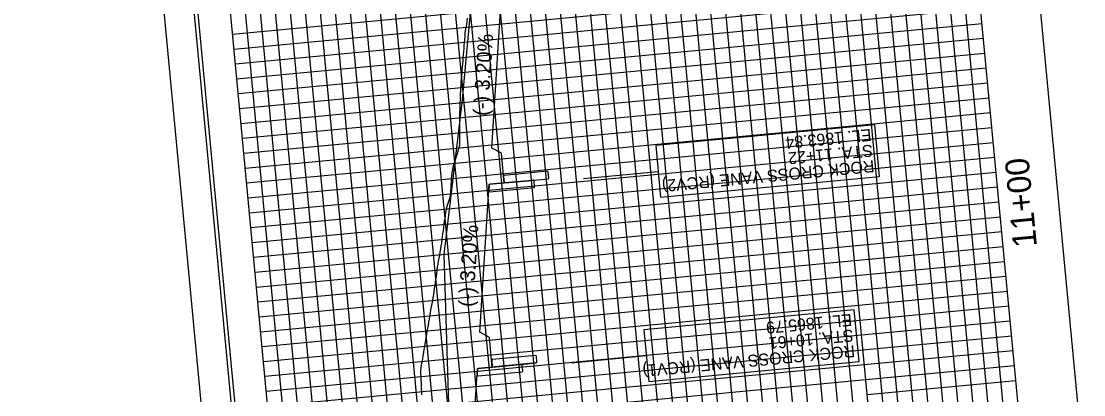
# Model space of a CAD drawing. Extents: x 554635 to 555260, y 497951 to 498841.
# Drawn here: x 554635.2 to 554990.7, y 498156.2 to 498281.2 of the extents above; entities that cross this region are included whole.
import ezdxf

# ---------------------------------------------------------------- set-up
doc = ezdxf.new("R2010")
doc.units = 0
for name, color, linetype in [('Exist Vertical Profile Ground Line', 7, 'Continuous'), ('Exist Vertical Profile Horizontal Axis Label Major', 7, 'Continuous'), ('Prop Drainage Ditch Boundaries', 7, 'Continuous'), ('Prop Erosion Rip Rap Single Stone CELL', 7, 'Continuous'), ('Prop Plan Preparation Sheet Bridge Report Non FEMA CELL', 7, 'Continuous'), ('Prop Vertical Profile Ditch Grade Median', 7, 'Continuous'), ('Prop Vertical Profile Ditch Grade Median Label', 7, 'Continuous'), ('Prop VPI Ditch Grade Median Label', 7, 'Continuous'), ('Prop VPT Ditch Grade Median Label', 7, 'Continuous'), ('Scratch_Level_3', 7, 'Continuous'), ('Sheet Layout Plan Border', 7, 'Continuous'), ('Sheet Plan CELL', 7, 'Continuous'), ('Sheet Plot Border Inside CELL', 7, 'Continuous'), ('Sheet Plot Border Outside CELL', 7, 'Continuous')]:
    doc.layers.add(name, color=color, linetype=linetype)

msp = doc.modelspace()

# ---------------------------------------------------------------- linework, layer by layer
at = {"layer": 'Exist Vertical Profile Ground Line'}
for points in [[(554775.22, 498202.97), (554775.39, 498203.99), (554775.56, 498205.01), (554775.73, 498206.03), (554775.9, 498207.05), (554776.07, 498208.07), (554776.21, 498209.09), (554776.33, 498210.11), (554776.46, 498211.12), (554776.58, 498212.14), (554776.73, 498213.16), (554776.88, 498214.18), (554777.03, 498215.2), (554777.17, 498216.21), (554777.32, 498217.23), (554777.47, 498218.25), (554777.71, 498219.28), (554778.04, 498220.31), (554778.37, 498221.35), (554778.7, 498222.39), (554778.91, 498223.41), (554778.98, 498224.42), (554779.04, 498225.43), (554779.1, 498226.44), (554779.17, 498227.45), (554779.23, 498228.46), (554779.29, 498229.47), (554779.45, 498230.49), (554779.61, 498231.51), (554779.77, 498232.53), (554780.08, 498233.57), (554780.4, 498234.6), (554780.72, 498235.63), (554781.04, 498236.67), (554781.36, 498237.7), (554781.67, 498238.74), (554781.99, 498239.77), (554781.99, 498240.78), (554782, 498241.78), (554782, 498242.79), (554782.01, 498243.79), (554782, 498244.8), (554781.99, 498245.8), (554781.98, 498246.8), (554781.97, 498247.81), (554781.96, 498248.81), (554781.95, 498249.81), (554781.98, 498250.82), (554782.03, 498251.83), (554782.08, 498252.84), (554782.12, 498253.85), (554782.16, 498254.86), (554782.2, 498255.86), (554782.24, 498256.87), (554782.28, 498257.88), (554782.32, 498258.89), (554782.37, 498259.9), (554782.45, 498260.91), (554782.54, 498261.92), (554782.62, 498262.93), (554782.7, 498263.95), (554782.78, 498264.96), (554782.87, 498265.97), (554782.95, 498266.98), (554783.03, 498268), (554783.11, 498269.01), (554783.19, 498270.02), (554783.28, 498271.03), (554783.37, 498272.05), (554783.45, 498273.06), (554783.54, 498274.07), (554783.62, 498275.08), (554783.71, 498276.1), (554783.79, 498277.11), (554783.91, 498278.12), (554784.09, 498279.14), (554784.27, 498280.17), (554784.44, 498281.19), (554784.53, 498282.2)], [(554769.26, 498156.2), (554769.22, 498157.2), (554769.18, 498158.2), (554769.14, 498159.2), (554769.1, 498160.21), (554769.06, 498161.21), (554769.01, 498162.21), (554768.95, 498163.21), (554768.9, 498164.2), (554769.01, 498165.22), (554769.18, 498166.24), (554769.36, 498167.26), (554769.54, 498168.28), (554769.72, 498169.3), (554769.89, 498170.33), (554770.06, 498171.35), (554770.23, 498172.37), (554770.4, 498173.39), (554770.57, 498174.41), (554770.74, 498175.43), (554770.91, 498176.45), (554771.08, 498177.47), (554771.25, 498178.49), (554771.43, 498179.51), (554771.6, 498180.53), (554771.77, 498181.55), (554771.94, 498182.57), (554772.11, 498183.59), (554772.28, 498184.61), (554772.49, 498185.64), (554772.7, 498186.66), (554772.9, 498187.69), (554773.05, 498188.7), (554773.21, 498189.72), (554773.36, 498190.74), (554773.51, 498191.76), (554773.67, 498192.78), (554773.82, 498193.8), (554773.97, 498194.82), (554774.12, 498195.84), (554774.26, 498196.85), (554774.39, 498197.87), (554774.54, 498198.89), (554774.71, 498199.91), (554774.88, 498200.93), (554775.05, 498201.95), (554775.22, 498202.97)]]:
    msp.add_lwpolyline(points, dxfattribs=at)
at = {"layer": 'Prop Drainage Ditch Boundaries'}
msp.add_lwpolyline([(554756.46, 498100.75), (554778.24, 498153.03), (554776.77, 498203.12), (554782.76, 498253.91), (554787.47, 498304.58), (554794.13, 498350.41)], dxfattribs=at)
at = {"layer": 'Prop Erosion Rip Rap Single Stone CELL'}
for p, q in [((554811.28, 498230.99), (554796.78, 498229.62)), ((554796.59, 498229.27), (554796.77, 498227.44)), ((554804.78, 498227.86), (554797.01, 498227.13)), ((554806.54, 498228.03), (554804.78, 498227.86)), ((554806.54, 498228.03), (554809.33, 498228.29)), ((554806.96, 498225.89), (554806.79, 498227.72)), ((554809.33, 498228.29), (554811.52, 498228.5)), ((554811.7, 498228.85), (554811.53, 498230.68)), ((554791.8, 498226.36), (554791.68, 498224.5)), ((554792.05, 498224.15), (554806.78, 498225.54)), ((554797.01, 498227.13), (554792.1, 498226.67)), ((554807.55, 498166.85), (554788.14, 498165.02)), ((554807.55, 498166.85), (554788.14, 498165.02)), ((554792.63, 498167.62), (554792.8, 498165.79)), ((554792.63, 498167.62), (554792.8, 498165.79)), ((554792.63, 498167.62), (554792.8, 498165.79)), ((554792.63, 498167.62), (554792.8, 498165.79)), ((554807.32, 498169.34), (554792.81, 498167.97)), ((554807.32, 498169.34), (554792.81, 498167.97)), ((554807.32, 498169.34), (554792.81, 498167.97)), ((554807.32, 498169.34), (554792.81, 498167.97)), ((554805.36, 498166.65), (554807.55, 498166.85)), ((554805.36, 498166.65), (554807.55, 498166.85)), ((554805.36, 498166.65), (554807.55, 498166.85)), ((554805.36, 498166.65), (554807.55, 498166.85)), ((554807.74, 498167.21), (554807.56, 498169.03)), ((554807.74, 498167.21), (554807.56, 498169.03)), ((554807.74, 498167.21), (554807.56, 498169.03)), ((554807.74, 498167.21), (554807.56, 498169.03)), ((554787.84, 498164.71), (554787.72, 498162.86)), ((554787.84, 498164.71), (554787.72, 498162.86)), ((554787.84, 498164.71), (554787.72, 498162.86)), ((554787.84, 498164.71), (554787.72, 498162.86)), ((554788.08, 498162.5), (554802.81, 498163.9)), ((554788.08, 498162.5), (554802.81, 498163.9)), ((554788.08, 498162.5), (554802.81, 498163.9)), ((554788.08, 498162.5), (554802.81, 498163.9)), ((554793.05, 498165.48), (554788.14, 498165.02)), ((554793.05, 498165.48), (554805.36, 498166.65)), ((554793.05, 498165.48), (554805.36, 498166.65)), ((554793.05, 498165.48), (554800.81, 498166.22)), ((554800.81, 498166.22), (554793.05, 498165.48)), ((554802.58, 498166.38), (554800.81, 498166.22)), ((554802.58, 498166.38), (554805.36, 498166.65)), ((554802.99, 498164.25), (554802.82, 498166.07)), ((554802.99, 498164.25), (554802.82, 498166.07)), ((554802.99, 498164.25), (554802.82, 498166.07)), ((554802.99, 498164.25), (554802.82, 498166.07))]:
    msp.add_line(p, q, dxfattribs=at)
for points in [[(554797.01, 498227.13), (554804.78, 498227.86), (554806.54, 498228.03)], [(554802.58, 498166.38), (554800.81, 498166.22), (554793.05, 498165.48), (554788.14, 498165.02)], [(554793.05, 498165.48), (554800.81, 498166.22), (554802.58, 498166.38)], [(554800.81, 498166.22), (554802.58, 498166.38), (554805.36, 498166.65)]]:
    msp.add_lwpolyline(points, dxfattribs=at)
for centre, start, end in [((554792.02, 498224.48), 176.3197, 275.4008), ((554792.13, 498226.33), 95.4008, 176.3197), ((554788.17, 498164.69), 95.4008, 176.3197), ((554788.17, 498164.69), 95.4008, 176.3197), ((554788.17, 498164.69), 95.4008, 176.3197), ((554788.17, 498164.69), 95.4008, 176.3197), ((554788.05, 498162.83), 176.3197, 275.4008), ((554788.05, 498162.83), 176.3197, 275.4008), ((554788.05, 498162.83), 176.3197, 275.4008), ((554788.05, 498162.83), 176.3197, 275.4008)]:
    msp.add_arc(centre, 0.333, start, end, dxfattribs=at)
for centre, major_axis, start_param, end_param in [((554811.32, 498230.66), (-0.031, 0.332), 4.712389, 6.283185), ((554796.81, 498229.29), (0.031, -0.332), 3.141593, 4.712389), ((554796.98, 498227.46), (0.031, -0.332), 4.712389, 6.283185), ((554806.57, 498227.7), (-0.031, 0.332), 5.974663, 6.283185), ((554806.57, 498227.7), (-0.031, 0.332), 4.712389, 5.974663), ((554811.49, 498228.83), (0.031, -0.332), 0, 1.570796), ((554806.75, 498225.87), (0.031, -0.332), 0, 1.570796), ((554792.84, 498167.64), (0.031, -0.332), 3.141593, 4.712389), ((554792.84, 498167.64), (0.031, -0.332), 3.141593, 4.712389), ((554792.84, 498167.64), (0.031, -0.332), 3.141593, 4.712389), ((554792.84, 498167.64), (0.031, -0.332), 3.141593, 4.712389), ((554807.35, 498169.01), (-0.031, 0.332), 4.712389, 6.283185), ((554807.35, 498169.01), (-0.031, 0.332), 4.712389, 6.283185), ((554807.35, 498169.01), (-0.031, 0.332), 4.712389, 6.283185), ((554807.35, 498169.01), (-0.031, 0.332), 4.712389, 6.283185), ((554807.52, 498167.19), (0.031, -0.332), 0, 1.570796), ((554807.52, 498167.19), (0.031, -0.332), 0, 1.570796), ((554807.52, 498167.19), (0.031, -0.332), 0, 1.570796), ((554807.52, 498167.19), (0.031, -0.332), 0, 1.570796), ((554793.01, 498165.81), (0.031, -0.332), 4.712389, 6.283185), ((554793.01, 498165.81), (0.031, -0.332), 4.712389, 6.283185), ((554793.01, 498165.81), (0.031, -0.332), 4.712389, 6.283185), ((554793.01, 498165.81), (0.031, -0.332), 4.712389, 6.283185), ((554802.61, 498166.05), (-0.031, 0.332), 4.712389, 6.283185), ((554802.61, 498166.05), (-0.031, 0.332), 4.712389, 6.283185), ((554802.61, 498166.05), (-0.031, 0.332), 5.974663, 6.283185), ((554802.61, 498166.05), (-0.031, 0.332), 5.974663, 6.283185), ((554802.61, 498166.05), (-0.031, 0.332), 4.712389, 5.974663), ((554802.61, 498166.05), (-0.031, 0.332), 4.712389, 5.974663), ((554802.78, 498164.23), (0.031, -0.332), 0, 1.570796), ((554802.78, 498164.23), (0.031, -0.332), 0, 1.570796), ((554802.78, 498164.23), (0.031, -0.332), 0, 1.570796), ((554802.78, 498164.23), (0.031, -0.332), 0, 1.570796)]:
    msp.add_ellipse(centre, major_axis=major_axis, ratio=0.64, start_param=start_param, end_param=end_param, dxfattribs=at)
at = {"layer": 'Prop Plan Preparation Sheet Bridge Report Non FEMA CELL'}
for p, q in [((554975.22, 498084.39), (554938.81, 498469.55)), ((554892.11, 498113.58), (554859.16, 498462.02)), ((554897.09, 498114.05), (554864.14, 498462.49)), ((554902.06, 498114.52), (554869.12, 498462.96)), ((554907.04, 498114.99), (554874.1, 498463.43)), ((554912.02, 498115.46), (554879.08, 498463.9)), ((554917, 498115.93), (554884.05, 498464.38)), ((554925.45, 498079.69), (554889.03, 498464.85)), ((554925.45, 498079.69), (554889.03, 498464.85)), ((554926.95, 498116.87), (554894.01, 498465.32)), ((554857.26, 498110.28), (554824.32, 498458.73)), ((554862.24, 498110.75), (554829.3, 498459.2)), ((554867.22, 498111.22), (554834.28, 498459.67)), ((554875.67, 498074.98), (554839.25, 498460.14)), ((554877.17, 498112.16), (554844.23, 498460.61)), ((554882.15, 498112.64), (554849.21, 498461.08)), ((554887.13, 498113.11), (554854.19, 498461.55)), ((554817.44, 498106.52), (554784.5, 498454.96)), ((554825.89, 498070.27), (554789.48, 498455.43)), ((554827.4, 498107.46), (554794.45, 498455.9)), ((554832.37, 498107.93), (554799.43, 498456.38)), ((554837.35, 498108.4), (554804.41, 498456.85)), ((554842.33, 498108.87), (554809.39, 498457.32)), ((554847.31, 498109.34), (554814.36, 498457.79)), ((554852.29, 498109.81), (554819.34, 498458.26)), ((554777.62, 498102.75), (554744.68, 498451.2)), ((554782.6, 498103.22), (554749.65, 498451.67)), ((554787.57, 498103.69), (554754.63, 498452.14)), ((554792.55, 498104.16), (554759.61, 498452.61)), ((554797.53, 498104.63), (554764.59, 498453.08)), ((554802.51, 498105.11), (554769.56, 498453.55)), ((554807.48, 498105.58), (554774.54, 498454.02)), ((554812.46, 498106.05), (554779.52, 498454.49)), ((554742.77, 498099.46), (554709.83, 498447.9)), ((554747.75, 498099.93), (554714.81, 498448.37)), ((554752.73, 498100.4), (554719.79, 498448.85)), ((554757.71, 498100.87), (554724.76, 498449.32)), ((554762.68, 498101.34), (554729.74, 498449.79)), ((554767.66, 498101.81), (554734.72, 498450.26)), ((554776.11, 498065.57), (554739.7, 498450.73)), ((554726.33, 498060.86), (554689.92, 498446.02)), ((554727.84, 498098.05), (554694.9, 498446.49)), ((554732.82, 498098.52), (554699.87, 498446.96)), ((554737.8, 498098.99), (554704.85, 498447.43)), ((554946.86, 498118.75), (554921.8, 498383.85)), ((554951.84, 498119.22), (554926.78, 498384.32)), ((554956.82, 498119.69), (554931.76, 498384.79)), ((554961.8, 498120.16), (554936.73, 498385.26)), ((554966.77, 498120.64), (554941.71, 498385.73)), ((554931.93, 498117.34), (554906.87, 498382.44)), ((554936.91, 498117.81), (554911.84, 498382.91)), ((554941.89, 498118.28), (554916.82, 498383.38)), ((554905.03, 498295.6), (554705.92, 498276.78)), ((554905.5, 498290.62), (554706.39, 498271.8)), ((554905.97, 498285.65), (554706.86, 498266.82)), ((554956.22, 498285.37), (554906.44, 498280.67)), ((554906.44, 498280.67), (554707.33, 498261.84)), ((554956.69, 498280.4), (554906.91, 498275.69)), ((554906.91, 498275.69), (554707.8, 498256.87)), ((554957.16, 498275.42), (554907.39, 498270.71)), ((554907.39, 498270.71), (554708.27, 498251.89)), ((554957.63, 498270.44), (554907.86, 498265.73)), ((554907.86, 498265.73), (554708.74, 498246.91)), ((554958.1, 498265.46), (554908.33, 498260.76)), ((554908.33, 498260.76), (554709.21, 498241.93)), ((554958.58, 498260.48), (554908.8, 498255.78)), ((554908.8, 498255.78), (554709.69, 498236.95)), ((554959.05, 498255.51), (554909.27, 498250.8)), ((554909.27, 498250.8), (554710.16, 498231.98)), ((554959.52, 498250.53), (554909.74, 498245.82)), ((554909.74, 498245.82), (554710.63, 498227)), ((554959.99, 498245.55), (554910.21, 498240.85)), ((554910.21, 498240.85), (554711.1, 498222.02)), ((554960.46, 498240.57), (554910.68, 498235.87)), ((554910.68, 498235.87), (554711.57, 498217.04)), ((554960.93, 498235.6), (554911.15, 498230.89)), ((554911.15, 498230.89), (554712.04, 498212.06)), ((554961.4, 498230.62), (554911.62, 498225.91)), ((554911.62, 498225.91), (554712.51, 498207.09)), ((554961.87, 498225.64), (554912.09, 498220.93)), ((554912.09, 498220.93), (554712.98, 498202.11)), ((554962.34, 498220.66), (554912.56, 498215.96)), ((554912.56, 498215.96), (554713.45, 498197.13)), ((554962.81, 498215.68), (554913.03, 498210.98)), ((554913.03, 498210.98), (554713.92, 498192.15)), ((554963.28, 498210.71), (554913.5, 498206)), ((554913.5, 498206), (554714.39, 498187.18)), ((554963.75, 498205.73), (554913.97, 498201.02)), ((554913.97, 498201.02), (554714.86, 498182.2)), ((554964.22, 498200.75), (554914.44, 498196.04)), ((554914.44, 498196.04), (554715.33, 498177.22)), ((554964.69, 498195.77), (554914.92, 498191.07)), ((554914.92, 498191.07), (554715.8, 498172.24)), ((554965.16, 498190.8), (554915.39, 498186.09)), ((554915.39, 498186.09), (554716.27, 498167.26)), ((554965.63, 498185.82), (554915.86, 498181.11)), ((554915.86, 498181.11), (554716.74, 498162.29)), ((554966.11, 498180.84), (554916.33, 498176.13)), ((554916.33, 498176.13), (554717.21, 498157.31)), ((554966.58, 498175.86), (554916.8, 498171.16)), ((554916.8, 498171.16), (554717.69, 498152.33)), ((554967.05, 498170.88), (554917.27, 498166.18)), ((554917.27, 498166.18), (554718.16, 498147.35)), ((554967.52, 498165.91), (554917.74, 498161.2)), ((554917.74, 498161.2), (554718.63, 498142.38)), ((554967.99, 498160.93), (554918.21, 498156.22))]:
    msp.add_line(p, q, dxfattribs=at)
at = {"layer": 'Prop Vertical Profile Ditch Grade Median'}
msp.add_lwpolyline([(554783.89, 498103.35), (554787.86, 498164.99), (554792.83, 498165.46), (554791.89, 498175.42), (554788.62, 498177.12), (554791.82, 498226.64), (554796.8, 498227.11), (554795.86, 498237.07), (554792.63, 498238.77), (554795.79, 498288.29), (554800.76, 498288.76), (554799.82, 498298.71), (554796.6, 498300.42), (554799.85, 498350.97)], dxfattribs=at)
at = {"layer": 'Prop VPT Ditch Grade Median Label'}
for p, q in [((554823.31, 498228.61), (554848.31, 498230.98)), ((554819.34, 498166.96), (554844.34, 498169.33))]:
    msp.add_line(p, q, dxfattribs=at)
for points in [[(554922.4, 498229.23), (554920.76, 498246.58), (554847.49, 498239.65), (554849.13, 498222.3)], [(554915.52, 498167.3), (554913.88, 498184.66), (554843.52, 498178), (554845.16, 498160.65)]]:
    msp.add_lwpolyline(points, close=True, dxfattribs=at)
for points in [[(554922.4, 498229.23), (554920.76, 498246.58), (554847.49, 498239.65), (554849.13, 498222.3), (554922.4, 498229.23)], [(554915.52, 498167.3), (554913.88, 498184.66), (554843.52, 498178), (554845.16, 498160.65), (554915.52, 498167.3)]]:
    msp.add_lwpolyline(points, dxfattribs=at)
at = {"layer": 'Scratch_Level_3'}
for p, q in [((554807.55, 498166.85), (554800.81, 498166.22)), ((554807.55, 498166.85), (554800.81, 498166.22)), ((554802.99, 498164.25), (554802.82, 498166.07)), ((554802.99, 498164.25), (554802.82, 498166.07))]:
    msp.add_line(p, q, dxfattribs=at)
msp.add_arc((554788.17, 498164.69), 0.333, 95.4008, 176.3197, dxfattribs=at)
msp.add_arc((554788.17, 498164.69), 0.333, 95.4008, 176.3197, dxfattribs=at)
for centre, major_axis, start_param, end_param in [((554802.61, 498166.05), (-0.031, 0.332), 4.712389, 6.283185), ((554802.61, 498166.05), (-0.031, 0.332), 4.712389, 6.283185), ((554802.78, 498164.23), (0.031, -0.332), 0, 1.570796), ((554802.78, 498164.23), (0.031, -0.332), 0, 1.570796)]:
    msp.add_ellipse(centre, major_axis=major_axis, ratio=0.64, start_param=start_param, end_param=end_param, dxfattribs=at)
at = {"layer": 'Sheet Layout Plan Border'}
msp.add_lwpolyline([(555232.94, 498108.76), (555192.39, 498537.63), (554954.42, 498515.13), (554994.97, 498086.26)], close=True, dxfattribs=at)
msp.add_lwpolyline([(555232.94, 498108.76), (555192.39, 498537.63), (554954.42, 498515.13), (554994.97, 498086.26)], close=True, dxfattribs=at)
at = {"layer": 'Sheet Plan CELL'}
msp.add_lwpolyline([(554647.23, 498781.63), (554717.82, 498034.95), (555240.49, 498084.36), (555169.9, 498831.04)], close=True, dxfattribs=at)
at = {"layer": 'Sheet Plot Border Inside CELL'}
msp.add_lwpolyline([(555248.96, 498008.08), (555170.55, 498837.37), (554645.4, 498787.73), (554723.81, 497958.43)], close=True, dxfattribs=at)
at = {"layer": 'Sheet Plot Border Outside CELL'}
msp.add_lwpolyline([(555259.53, 498002.55), (555180.3, 498840.56), (554635.23, 498789.03), (554714.46, 497951.01)], close=True, dxfattribs=at)

# ---------------------------------------------------------------- texts
at = {"layer": 'Exist Vertical Profile Horizontal Axis Label Major'}
msp.add_text('11+00', height=8, rotation=95.4008, dxfattribs=at).set_placement((554975.04, 498205.91))
at = {"layer": 'Prop Vertical Profile Ditch Grade Median Label'}
for p in [(554791.37, 498249.43), (554786.44, 498185.5)]:
    msp.add_text('(-) 3.20%', height=5, rotation=86.2991, dxfattribs=at).set_placement(p)
at = {"layer": 'Prop VPI Ditch Grade Median Label'}
for s, p in [('EL. 1863.84', (554919.45, 498245.19)), ('STA. 11+22 ', (554919.95, 498239.97)), ('ROCK CROSS VANE (RCV2)', (554920.44, 498234.75)), ('EL. 1865.79', (554912.96, 498183.3)), ('STA. 10+61 ', (554913.45, 498178.08)), ('ROCK CROSS VANE (RCV1)', (554913.95, 498172.86))]:
    msp.add_text(s, height=4, rotation=185.4008, dxfattribs=at).set_placement(p)

doc.saveas('drawing.dxf')
